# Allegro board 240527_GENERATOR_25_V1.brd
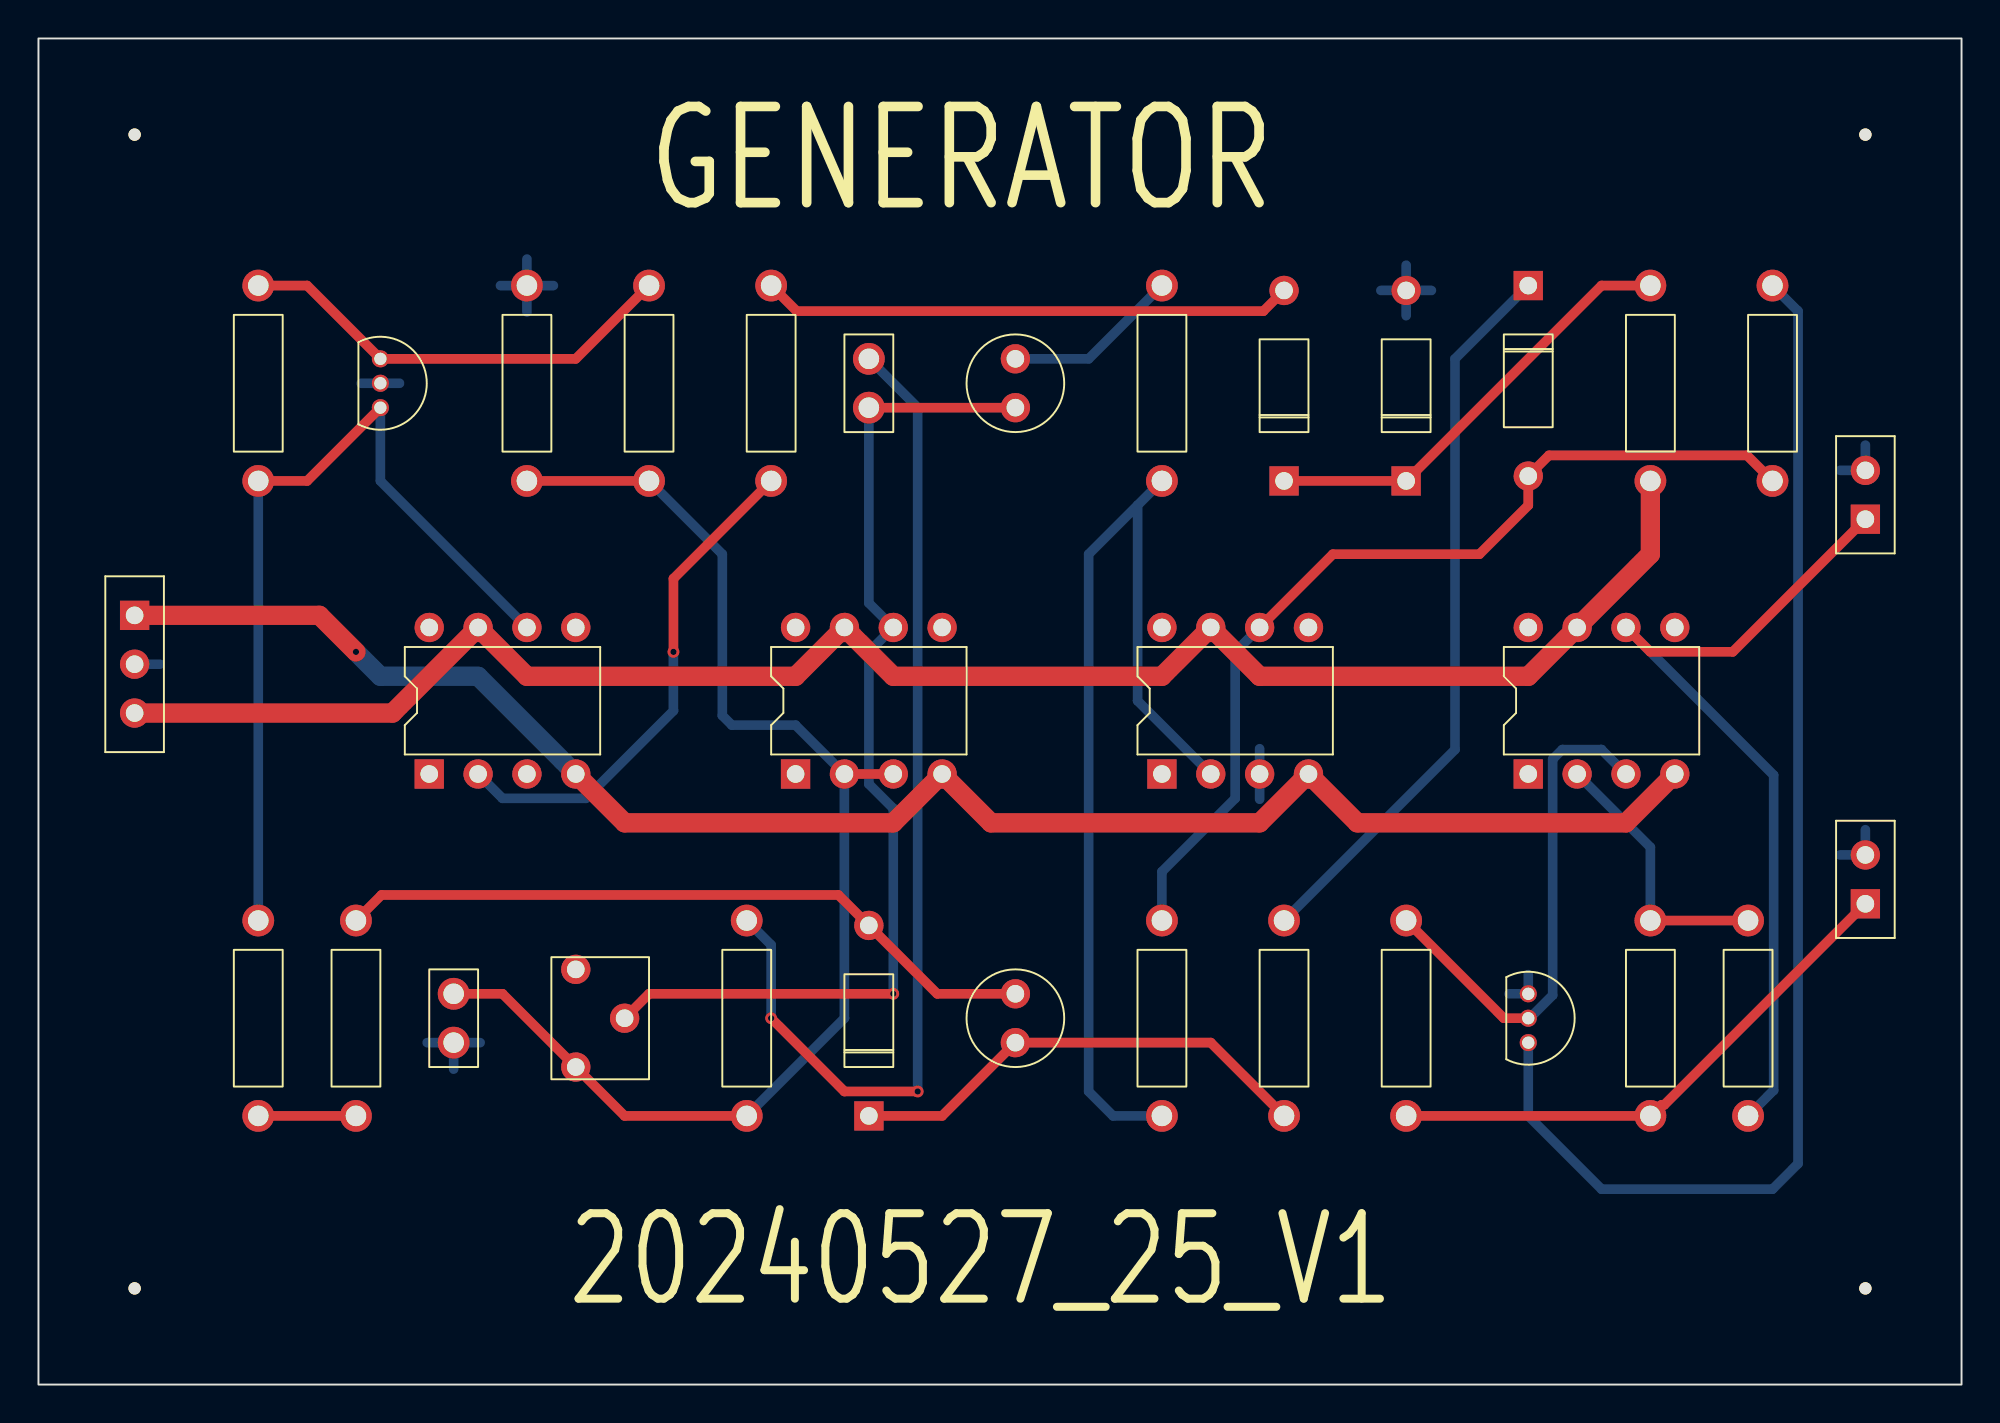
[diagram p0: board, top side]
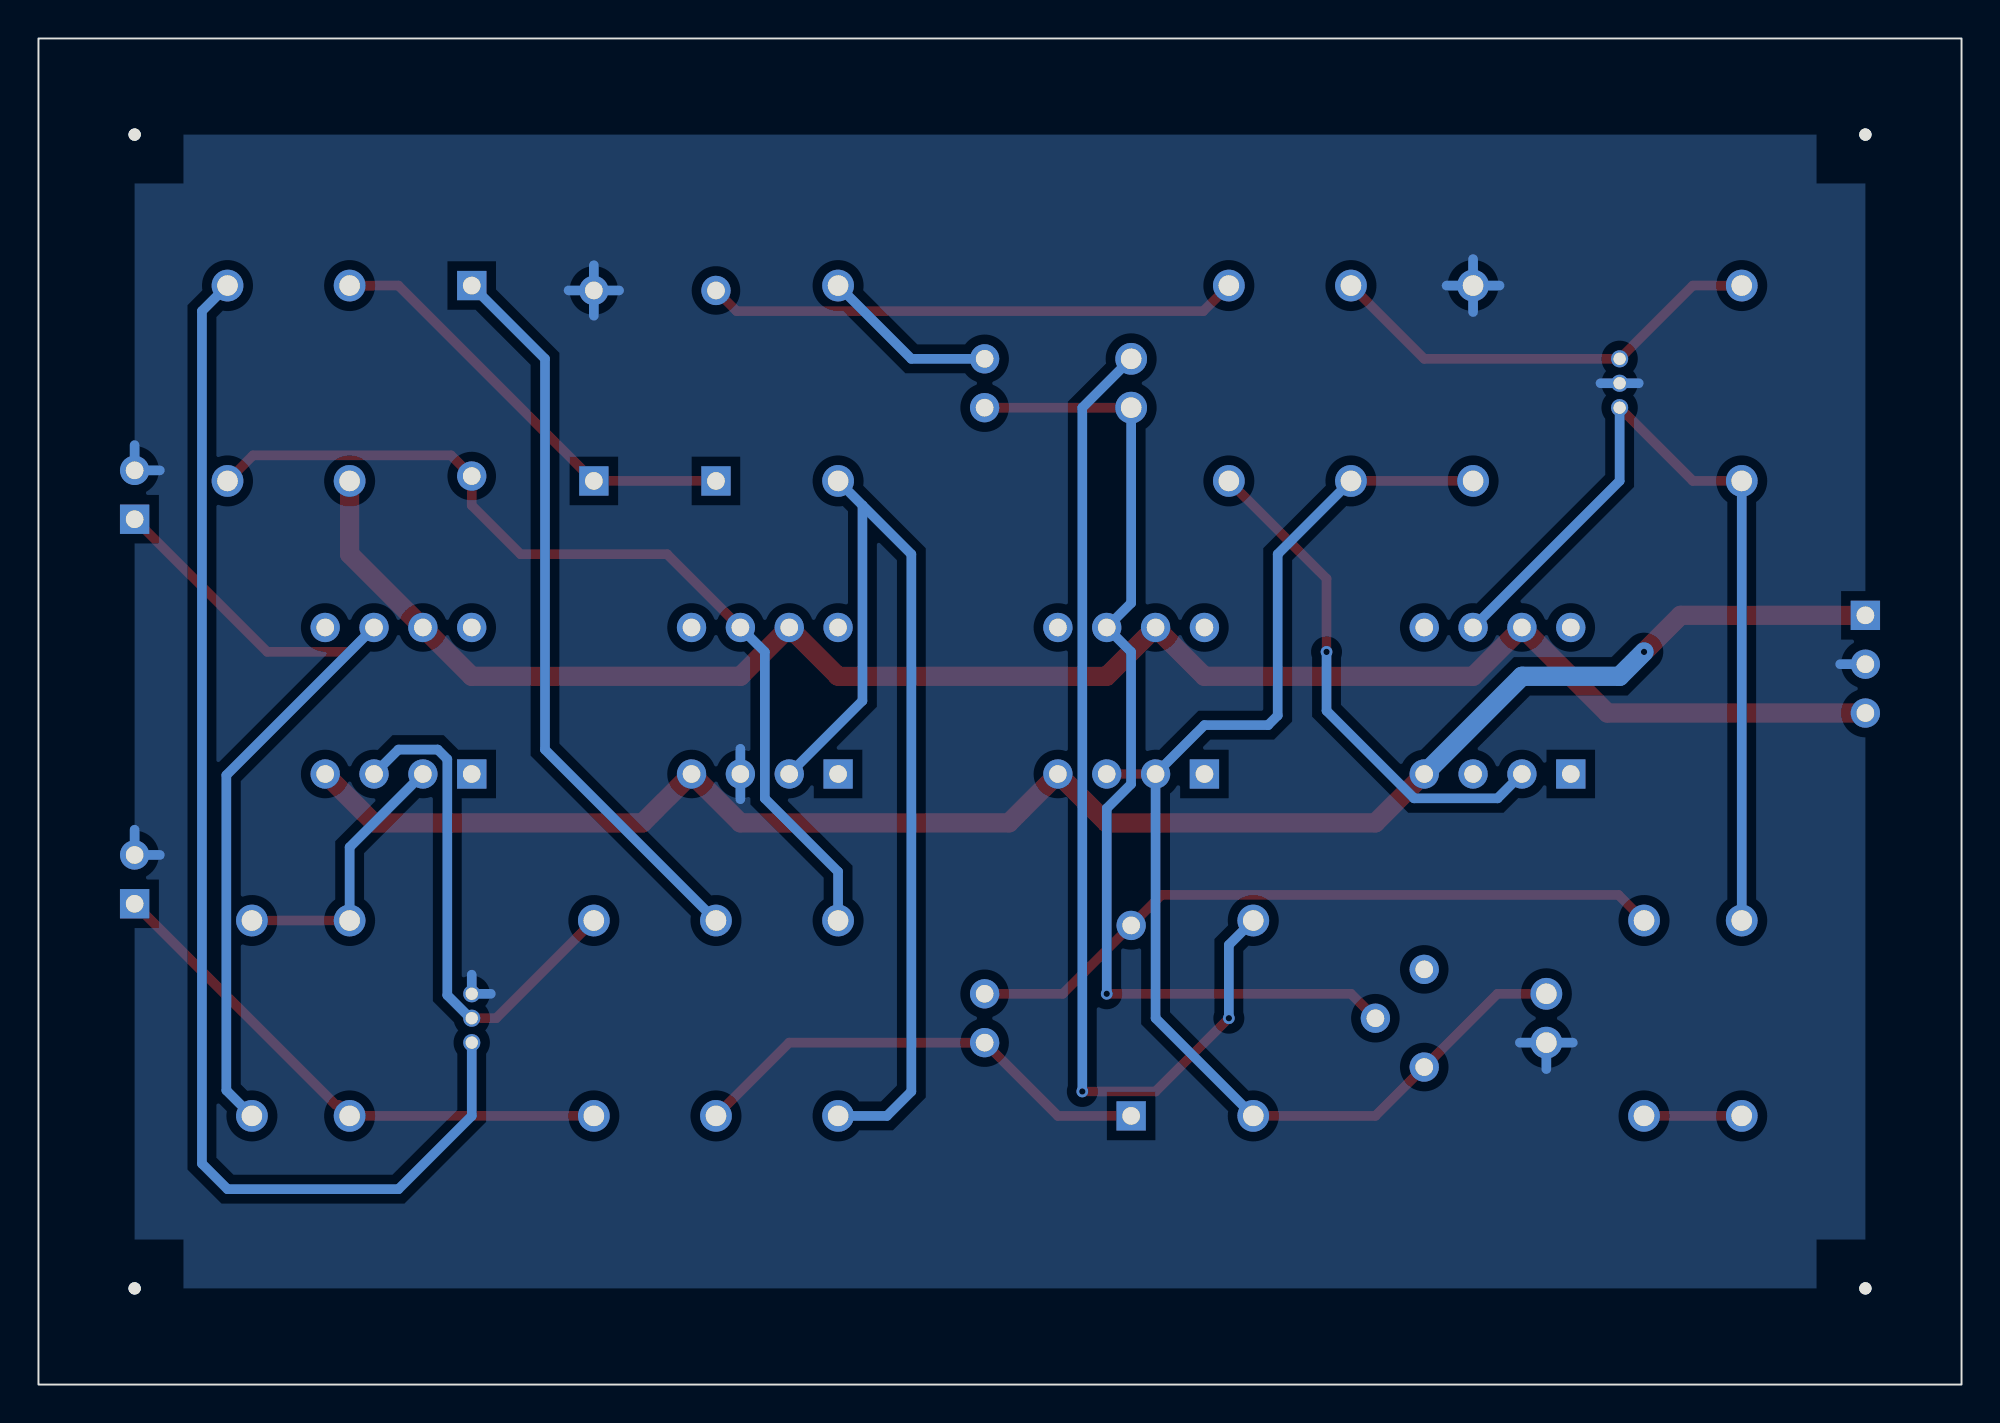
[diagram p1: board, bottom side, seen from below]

Outline 100 x 70 mm; copper layers: TOP, BOTTOM. Coordinates in mm from the lower left corner of the outline.
Outline path: rectangle 0,0 100,70

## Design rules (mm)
nets with their own width: min track width 1; nets +V -V GND

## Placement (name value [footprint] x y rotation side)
C1  0.0047uF  [CAPCK05]  43.18 53.34 180 top
C2  CAP POL  [CAP196]  50.8 50.8 0 top
C3  0.0047uF  [CAPCK05]  21.59 20.32 180 top
C5  10uF  [CAP196]  50.8 17.78 0 top
D1  1S1588  [DO41]  64.77 46.99 0 top
D2  RD 5.1E  [DO41]  71.12 46.99 0 top
D3  1S1588  [DO41]  77.47 57.15 180 top
D4  RD 5.1E  [DO41]  43.18 13.97 0 top
J1  -  [CON3]  5 40 0 top
J2  -  [CON2]  95 25 180 top
J3  -  [CON2]  95 45 180 top
NOREF  -  [unnamed]  95 65 0 top
NOREF#2  -  [unnamed]  95 5 0 top
NOREF#3  -  [#2]  95 5 90 top
NOREF#4  -  [#2]  95 65 0 top
NOREF#5  -  [unnamed]  5 5 0 top
NOREF#6  -  [#2]  0 70 0 top
NOREF#7  -  [#2]  0 70 0 top
NOREF#8  -  [#2]  0 0 90 top
NOREF#9  -  [#2]  5 40 90 top
NOREF#10  -  [#2]  5 65 90 top
NOREF#11  -  [#2]  2 68 0 top
NOREF#12  -  [#2]  95 25 90 top
NOREF#13  -  [#2]  100 0 90 top
NOREF#14  -  [#2]  0 0 90 top
NOREF#15  -  [#2]  5 5 90 top
NOREF#16  -  [unnamed]  5 65 0 top
Q1  C1815  [TO92]  77.47 20.32 0 top
Q2  K30  [TO92]  17.78 53.34 0 top
R1  3.3K  [RES400]  83.82 46.99 0 top
R2  10K  [RES400]  38.1 57.15 180 top
R3  3.3K  [RES400]  58.42 13.97 0 top
R4  10K  [RES400]  83.82 24.13 180 top
R5  3K  [RES400]  36.83 13.97 0 top
R6  10K  [RES400]  71.12 24.13 180 top
R7  10K  [RES400]  88.9 13.97 0 top
R8  R  [RES400]  58.42 46.99 0 top
R9  1K  [RES400]  31.75 46.99 0 top
R10  3K  [RES400]  25.4 46.99 0 top
R11  100K  [RES400]  11.43 57.15 180 top
R12  100K  [RES400]  11.43 24.13 180 top
R13  2K  [RES400]  16.51 13.97 0 top
R14  10K  [RES400]  64.77 13.97 0 top
R15  1K  [RES400]  90.17 46.99 0 top
U1  LF356  [DIP8_3]  20.32 31.75 90 top
U2  LF356  [DIP8_3]  39.37 31.75 90 top
U3  LF356  [DIP8_3]  58.42 31.75 90 top
U4  LF356  [DIP8_3]  77.47 31.75 90 top
VR1  4.7K  [RESADJ]  27.94 16.51 180 top

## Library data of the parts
C1 C3 = CAP NP: Tolerance: ***; User Part Number: ***
C2 C5 = CAP POL: Tolerance: ***; User Part Number: ***
D1 D3 = DIODE
D2 D4 = DIODE ZENER
J1 = CON3
J2 J3 = CON2
Q1 = NPN ECB
Q2 = JFET N SDG
R1-R15 = R: Tolerance: ***; User Part Number: ***
U1-U4 = LF356: Tolerance: ***; User Part Number: ***
VR1 = RESISTOR VAR 2: Tolerance: ***; User Part Number: ***

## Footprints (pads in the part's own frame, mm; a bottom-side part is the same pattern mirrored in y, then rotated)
CAP196
  round 1.524 hole 0.914: 1(0,0) 2(0,2.54)
CAPCK05
  round 1.651 hole 1.067: 1(0,0) 2(0,2.54)
CON2
  rect 1.524x1.524 hole 0.914: 1(0,0)
  round 1.524 hole 0.914: 2(0,-2.54)
CON3
  rect 1.524x1.524 hole 0.914: 1(0,0)
  round 1.524 hole 0.914: 2(0,-2.54) 3(0,-5.08)
DIP8_3
  rect 1.524x1.524 hole 0.914: 1(0,0)
  round 1.524 hole 0.914: 2(0,-2.54) 3(0,-5.08) 4(0,-7.62) 5(7.62,-7.62) 6(7.62,-5.08) 7(7.62,-2.54) 8(7.62,0)
DO41
  rect 1.524x1.524 hole 0.914: 1(0,0)
  round 1.524 hole 0.914: 2(0,9.906)
RES400
  round 1.651 hole 1.067: 1(0,0) 2(0,10.16)
RESADJ
  round 1.524 hole 0.914: 1(0,0) 2(-2.54,-2.54) 3(0,-5.08)
TO92
  round 0.889 hole 0.635: 1(0,0) 2(0,-1.27) 3(0,-2.54)
unnamed
  round 0.635 hole 3 unplated: (0,0)

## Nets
GND: C3.2 D2.2(ANODE) J1.2 J2.2 J3.2 Q1.1(E) Q2.2(D) R10.2 U1.3(+IN) U3.3(+IN)
+V: J1.1 U1.4(V-) U2.4(V-) U3.4(V-) U4.4(V-)
-V: J1.3 R1.1 U1.7(V+) U2.7(V+) U3.7(V+) U4.7(V+)
OUT_1: J2.1 R4.2 R6.2
OUT_2: J3.1 R7.1 U4.6(OUT)
SIG_1: Q2.3(G) R11.2 R12.1 U1.6(OUT)
N01616: D1.1(K) D2.1(CATHODE) R1.2
N01636: D1.2(A) R2.1
N01640: R2.2 U1.2(-IN)
N01654: R3.1 R8.1 U3.2(-IN)
N01670: C2.2 R8.2
N01674: C1.2 C2.1 U2.6(OUT) VR1.2
N01678: C3.1 R5.1 R9.1 R10.1 U2.2(-IN) U2.3(+IN) VR1.1
N01713: C1.1 R5.2
N01735: Q2.1(S) R9.2 R11.1
N01746: R12.2 R13.1
N01750: C5.2 D4.2(ANODE) R13.2
N01754: C5.1 D4.1(CATHODE) R14.1
N01758: D3.1(K) R14.2
N01762: D3.2(A) R3.2 R15.1 U3.6(OUT)
N01766: Q1.3(B) R15.2
N02360: Q1.2(C) R6.1 U4.3(+IN)
N02374: R4.1 R7.2 U4.2(-IN)

Pads without a net: U1 1 5 8; U2 1 5 8; U3 1 5 8; U4 1 5 8; VR1 3

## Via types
v1: diameter 0.61, hole 0.33, TOP to BOTTOM, 5 vias

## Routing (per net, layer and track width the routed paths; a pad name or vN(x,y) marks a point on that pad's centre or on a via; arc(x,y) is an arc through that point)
GND: length 28.1
  BOTTOM w0.5: 93.69,27.54 J2.2 95,28.85 ; 16.78,52.07 Q2.2 18.78,52.07 ; 63.5,30.44 U3.3 63.5,33.06 ; R10.2 25.4,58.53 ; R10.2 24.02,57.15 ; R10.2 25.4,55.77 ; R10.2 26.78,57.15 ; 71.12,55.58 D2.2 ; D2.2 69.81,56.9 ; D2.2 72.43,56.9 ; D2.2 71.12,58.21 ; C3.2 22.97,17.78 ; C3.2 20.21,17.78 ; C3.2 21.59,16.4 ; 93.69,47.54 J3.2 95,48.85 ; 76.47,20.32 Q1.1 77.47,21.32 ; J1.2 6.31,37.46
+V: length 89.8
  TOP w1: v1(16.51,38.1) 14.61,40 J1.1 ; U1.4 30.48,29.21 44.45,29.21 U2.4 49.53,29.21 63.5,29.21 U3.4 68.58,29.21 82.55,29.21 U4.4
  BOTTOM w1: v1(16.51,38.1) 17.78,36.83 22.86,36.83 U1.4
-V: length 92.4
  TOP w1: R1.1 83.82,43.18 U4.7 77.47,36.83 63.5,36.83 U3.7 58.42,36.83 44.45,36.83 U2.7 39.37,36.83 25.4,36.83 U1.7 18.41,34.92 J1.3
OUT_1: length 28.4
  TOP w0.5: R6.2 R4.2 84.39,14.54 84.54,14.54 J2.1
OUT_2: length 45
  TOP w0.5: J3.1 88.1,38.1 83.82,38.1 U4.6
  BOTTOM w0.5: U4.6 90.23,31.69 90.23,15.3 R7.1
SIG_1: length 45.4
  TOP w0.5: Q2.3 13.97,46.99 R11.2
  BOTTOM w0.5: R11.2 R12.1 ; Q2.3 17.78,46.99 U1.6
N01616: length 23.3
  TOP w0.5: R1.2 81.28,57.15 D2.1 D1.1
N01636: length 27.7
  TOP w0.5: R2.1 39.43,55.82 63.69,55.82 D1.2
N01640: length 26.6
  TOP w0.5: R2.2 33.02,41.91 v1(33.02,38.1)
  BOTTOM w0.5: v1(33.02,38.1) 33.02,35.04 28.46,30.48 24.13,30.48 U1.2
N01654: length 53.2
  BOTTOM w0.5: R3.1 55.88,13.97 54.61,15.24 54.61,43.18 57.15,45.72 ; U3.2 57.15,35.56 57.15,45.72 ; R8.1 57.15,45.72
N01670: length 9.2
  BOTTOM w0.5: R8.2 54.61,53.34 C2.2
N01674: length 54.2
  TOP w0.5: VR1.2 31.75,20.32 v1(44.45,20.32) ; C1.2 C2.1
  BOTTOM w0.5: v1(44.45,20.32) 44.45,29.96 43.18,31.23 43.18,38.1 U2.6 43.18,40.64 C1.2
N01678: length 68
  TOP w0.5: U2.2 U2.3 ; R5.1 30.48,13.97 VR1.1 24.13,20.32 C3.1 ; R10.1 R9.1
  BOTTOM w0.5: R5.1 41.91,19.05 U2.2 39.37,34.29 36.06,34.29 35.56,34.79 35.56,43.18 R9.1
N01713: length 54
  TOP w0.5: v1(38.1,19.05) 41.91,15.24 v1(45.72,15.24)
  BOTTOM w0.5: v1(45.72,15.24) 45.72,50.8 C1.1 ; R5.2 38.1,22.86 v1(38.1,19.05)
N01735: length 23.5
  TOP w0.5: R9.2 27.94,53.34 Q2.1 13.97,57.15 R11.1
N01746: length 5.1
  TOP w0.5: R12.2 R13.1
N01750: length 37
  TOP w0.5: C5.2 46.74,20.32 D4.2 41.6,25.46 17.84,25.46 R13.2
N01754: length 24.7
  TOP w0.5: R14.1 60.96,17.78 C5.1 46.99,13.97 D4.1
N01758: length 38.3
  BOTTOM w0.5: D3.1 73.66,53.34 73.66,33.02 R14.2
N01762: length 49.2
  TOP w0.5: R15.1 88.84,48.32 78.55,48.32 D3.2 77.47,45.72 74.93,43.18 67.31,43.18 U3.6
  BOTTOM w0.5: R3.2 58.42,26.67 62.23,30.48 62.23,38.1 U3.6
N01766: length 66.2
  BOTTOM w0.5: R15.2 91.5,55.82 91.5,11.49 90.17,10.16 81.28,10.16 77.47,13.97 Q1.3
N02360: length 27
  TOP w0.5: Q1.2 76.2,19.05 R6.1
  BOTTOM w0.5: U4.3 81.28,33.02 79.24,33.02 78.74,32.52 78.74,20.25 77.54,19.05 Q1.2
N02374: length 14.3
  TOP w0.5: R4.1 R7.2
  BOTTOM w0.5: R4.1 83.82,27.94 U4.2

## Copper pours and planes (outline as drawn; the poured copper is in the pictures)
GND on BOTTOM: 5,5 5,65 95,65 95,5 ; 4 cut-outs

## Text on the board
Ref Des/Silkscreen Top: 20240527_25_V1 | GENERATOR
COMPVAL_TYPE_TOP: FIGURE | SIZE | 0.3302 | 0.635 | 0.9144 | 1.0668 | 3.0 | DRILL CHART: TOP to BOTTOM | ALL UNITS ARE IN MILLIMETERS | PLATED | NON-PLATED | QTY | 19 | 6 | 54 | 34 | 4
